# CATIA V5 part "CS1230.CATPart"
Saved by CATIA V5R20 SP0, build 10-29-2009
Part number: CS1230
Revision: 4
Definition: design
Nomenclature: CS1230
Source: made
Description: NOT SPECIFIED
Bounding box of the stored display mesh (mm): x -29 to 29, y -29 to 29, z -55 to 15
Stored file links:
  C:\Users\Raffaele\Desktop\3D X SITO CF\BOLEX\20-TILTED COLUMN SUPPORT\CS1230.CATPart
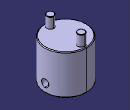
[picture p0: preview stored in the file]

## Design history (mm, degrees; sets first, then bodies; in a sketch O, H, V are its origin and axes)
Body1 "MANIFOLD_SOLID_BREP #715" (main body)
  Solid1: solid without history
